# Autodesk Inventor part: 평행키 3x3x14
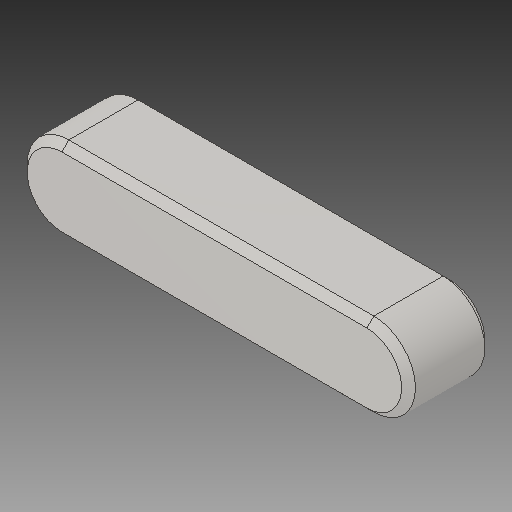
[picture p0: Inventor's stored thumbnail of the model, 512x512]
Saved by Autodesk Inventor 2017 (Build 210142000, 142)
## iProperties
Created: 2024-09
Part Number: 평행키 3x3x14
Material: 일반
Description: 키 및 해당 키홈
Document SubType Name: Modeling
Designer: MRC
Density: 1 g/cm^3
Appearance: 기본값
Author: jhkim
Sending System: Autodesk Inventor 2025
Preprocessor: ST-DEVELOPER v20
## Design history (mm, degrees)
feature "Solid1"
node "솔리드1"
